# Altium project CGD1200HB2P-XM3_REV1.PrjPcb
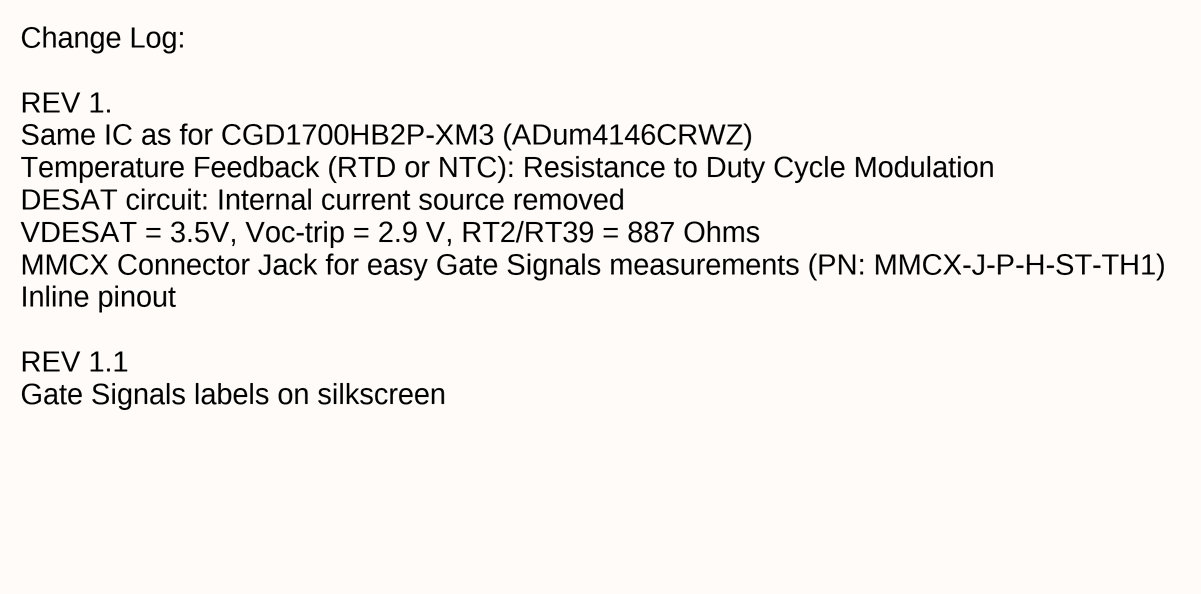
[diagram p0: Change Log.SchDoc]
5 sheets, 178 parts. Net scope: global (net labels, ports and power ports of the same name join across sheets).
Board file: CGD1200HB2P-XM3_REV1.PcbDoc
Sheets:
  Change Log.SchDoc
  Differential Signaling.SchDoc
  Gate Driver.SchDoc
  Power Supplies.SchDoc
  RTD.SchDoc

## Sheet Change Log.SchDoc
size 431 x 279 mm; Organization: ORGANIZATION; Address1: ADDRESS 1; Address2: ADDRESS 2; Address3: ADDRESS 3; Address4: ADDRESS 4; Revision: -; ENG_APP_DATE: --/--/--; DSN_APP_DATE: --/--/--; CHK_APP_DATE: --/--/--

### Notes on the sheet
- Change Log:
  REV 1.
  Same IC as for CGD1700HB2P-XM3 (ADum4146CRWZ)                                                                                                                                                                                                                  Temperature Feedback (RTD or NTC): Resistance to Duty Cycle Modulation                                                                                                                                                                                                     DESAT circuit: Internal current source removed                                                                                      VDESAT = 3.5V, Voc-trip = 2.9 V, RT2/RT39 = 887 Ohms	                                                                            MMCX Connector Jack for easy Gate Signals measurements (PN: MMCX-J-P-H-ST-TH1)
  Inline pinout
  REV 1.1
  Gate Signals labels on silkscreen

## Sheet Differential Signaling.SchDoc
size 431 x 279 mm; Organization: ORGANIZATION; Address1: ADDRESS 1; Address2: ADDRESS 2; Address3: ADDRESS 3; Address4: ADDRESS 4; Revision: -; ENG_APP_DATE: --/--/--; DSN_APP_DATE: --/--/--; CHK_APP_DATE: --/--/--
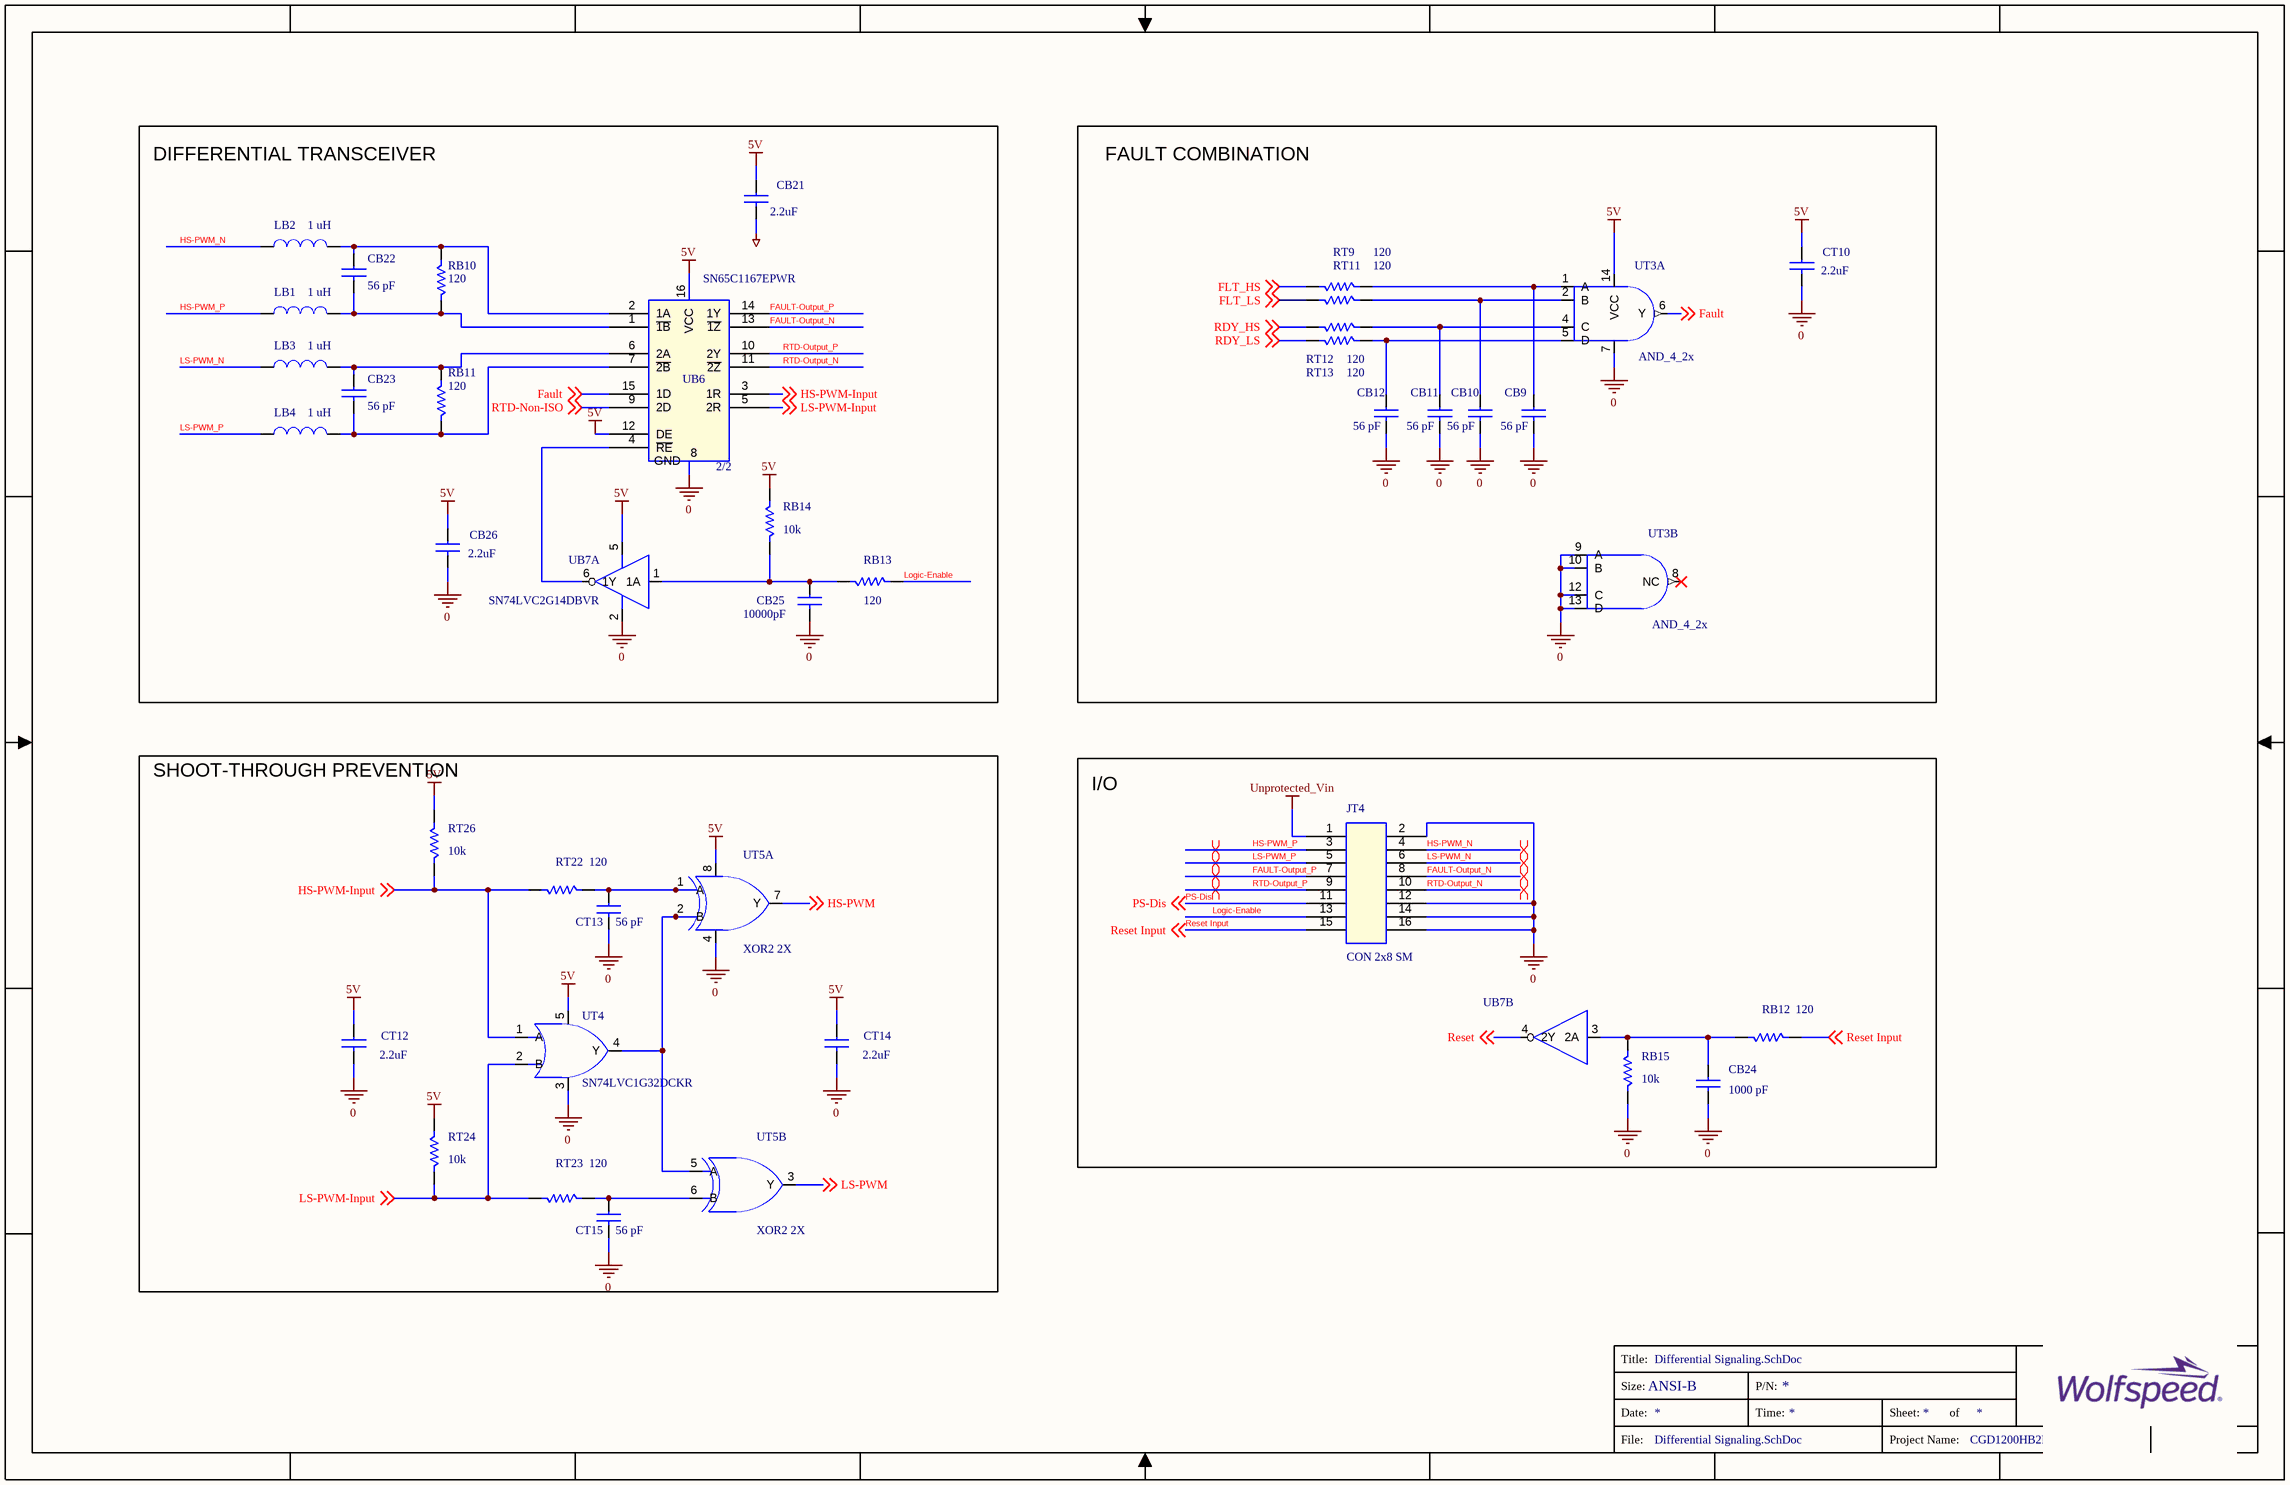
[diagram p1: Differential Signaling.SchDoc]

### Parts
CB9  56 pF  [CAPC1608X90N]
CB10  56 pF  [CAPC1608X90N]
CB11  56 pF  [CAPC1608X90N]
CB12  56 pF  [CAPC1608X90N]
CB21  2.2uF  [CAPC1608X90N]
CB22  56 pF  [CAPC1608X90N]
CB23  56 pF  [CAPC1608X90N]
CB24  1000 pF  [CAPC1608X90N]
CB25  10000pF  [CAPC1608X90N]
CB26  2.2uF  [CAPC1608X90N]
CT10  2.2uF  [CAPC1608X90N]
CT12  2.2uF  [CAPC1608X90N]
CT13  56 pF  [CAPC1608X90N]
CT14  2.2uF  [CAPC1608X90N]
CT15  56 pF  [CAPC1608X90N]
JT4  CON 2x8 SM  [CONN16_3020-16-0300-00_CNC]
LB1  1 uH  [INDC1608X95N]
LB2  1 uH  [INDC1608X95N]
LB3  1 uH  [INDC1608X95N]
LB4  1 uH  [INDC1608X95N]
RB10  120  [RESC1608X55N]
RB11  120  [RESC1608X55N]
RB12  120  [RESC1608X55N]
RB13  120  [RESC1608X55N]
RB14  10k  [RESC1608X55N]
RB15  10k  [RESC1608X55N]
RT9  120  [RESC1608X55N]
RT11  120  [RESC1608X55N]
RT12  120  [RESC1608X55N]
RT13  120  [RESC1608X55N]
RT22  120  [RESC1608X55N]
RT23  120  [RESC1608X55N]
RT24  10k  [RESC1608X55N]
RT26  10k  [RESC1608X55N]
UB6  2/2  Manufacturer PN: SN65C1167EPWR  [tssop_16]
UB7  SN74LVC2G14DBVR  [SOT95P280X145-6N_1]  (parts A,B of 2)
UT3  AND_4_2x  [D14]  (parts A,B of 2)
UT4  SN74LVC1G32DCKR  [SOT65P210X110-5N]
UT5  XOR2 2X  [US8_2P40X2P10_ONS]  (parts A,B of 2)

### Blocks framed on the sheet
DIFFERENTIAL TRANSCEIVER: CB21-CB23 CB25 CB26 LB1-LB4 RB10 RB11 RB13 RB14 UB6 UB7
FAULT COMBINATION: CB9-CB12 CT10 RT9 RT11-RT13 UT3
SHOOT-THROUGH PREVENTION: CT12-CT15 RT22-RT24 RT26 UT4 UT5
I/O: CB24 JT4 RB12 RB15 UB7

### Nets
0: CB9.2 CB10.2 CB11.2 CB12.2 CB21.2 CB24.2 CB25.2 CB26.2 CT10.2 CT12.2 CT13.2 CT14.2 CT15.2 JT4.2 JT4.12 JT4.14 JT4.16 RB15.1 UB6.8(GND) UB7.2(GND) UT3.7(GND) UT3.9(A) UT3.10(B) UT3.12(C) UT3.13(D) UT4.3(GND) UT5.4(GND)  [also labelled GND]
5V: CB21.1 CB26.1 CT10.1 CT12.1 CT14.1 RB14.2 RT24.2 RT26.2 UB6.12(DE) UB6.16(VCC) UB7.5(Vcc) UT3.14(VCC) UT4.5(Vcc) UT5.8(VCC)  [also labelled VCC]
Unprotected_Vin: JT4.1
Fault: UB6.15(1D) UT3.6(Y) ; off-sheet Fault
FAULT-Output_N: JT4.8 UB6.13(~{1Z})
FAULT-Output_P: JT4.7 UB6.14(1Y)
FLT_HS: RT9.1 ; off-sheet FLT_HS
FLT_LS: RT11.1 ; off-sheet FLT_LS
HS-PWM: UT5.7(Y) ; off-sheet HS-PWM
HS-PWM-Input: RT22.1 RT26.1 UB6.3(1R) UT4.1(A) ; off-sheet HS-PWM-Input
HS-PWM_N: JT4.4 LB2.1
HS-PWM_P: JT4.3 LB1.1
Logic-Enable: JT4.13 RB13.2
LS-PWM: UT5.3(Y) ; off-sheet LS-PWM
LS-PWM-Input: RT23.1 RT24.1 UB6.5(2R) UT4.2(B) ; off-sheet LS-PWM-Input
LS-PWM_N: JT4.6 LB3.1
LS-PWM_P: JT4.5 LB4.1
PS-Dis: JT4.11 ; off-sheet PS-Dis
RDY_HS: RT12.1 ; off-sheet RDY_HS
RDY_LS: RT13.1 ; off-sheet RDY_LS
Reset: UB7.4(2Y) ; off-sheet Reset
Reset Input: JT4.15 RB12.2 ; off-sheet Reset Input
RTD-Non-ISO: UB6.9(2D) ; off-sheet RTD-Non-ISO
RTD-Output_N: JT4.10 UB6.11(~{2Z})
RTD-Output_P: JT4.9 UB6.10(2Y)
NetCB9_1: CB9.1 RT9.2 UT3.1(A)
NetCB10_1: CB10.1 RT11.2 UT3.2(B)
NetCB11_1: CB11.1 RT12.2 UT3.4(C)
NetCB12_1: CB12.1 RT13.2 UT3.5(D)
NetCB22_1: CB22.1 LB2.2 RB10.2 UB6.2(1A)
NetCB22_2: CB22.2 LB1.2 RB10.1 UB6.1(~{1B})
NetCB23_1: CB23.1 LB3.2 RB11.2 UB6.6(2A)
NetCB23_2: CB23.2 LB4.2 RB11.1 UB6.7(~{2B})
NetCB24_1: CB24.1 RB12.1 RB15.2 UB7.3(2A)
NetCB25_1: CB25.1 RB13.1 RB14.1 UB7.1(1A)
NetCT13_1: CT13.1 RT22.2 UT5.1(A)
NetCT15_1: CT15.1 RT23.2 UT5.6(B)
NetUB6_4: UB6.4(~{RE}) UB7.6(1Y)
NetUT4_4: UT4.4(Y) UT5.2(B) UT5.5(A)

Not connected (* = marked no-connect by the designer): UT3 3(NC2) 8(NC)* 11(NC)

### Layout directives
differential pair: FAULT-Output_N, FAULT-Output_P, HS-PWM_N, HS-PWM_P, LS-PWM_N, LS-PWM_P, RTD-Output_N, RTD-Output_P

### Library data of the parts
CB9 CB10 = CAP_Dup1: CAP CER 56PF 50V C0G/NP0 0603; Manufacturer: Samsung Electro-Mechanics; Manufacturer PN: CL10C560JB8NNNC; Dielectric Type: Capacitors; Temperature Coefficient: C0G, NP0; Tolerance: 5%; CLASS: DISCRETE
CB11 CB12 CB22 CB23 CT13 CT15 = CAP_Dup1: CAP CER 56PF 50V C0G/NP0 0603; Manufacturer PN: CL10C560JB8NNNC; Manufacturer: Samsung Electro-Mechanics; CLASS: DISCRETE; Tolerance: 5%; Temperature Coefficient: C0G, NP0; Dielectric Type: Capacitors
CB21 CT10 CT12 CT14 = CAP_2.2uF: CAP CER 2.2UF 50V X5R 0603; Company Part Status: Obsolete; Manufacturer: Murata Electronics North America; Manufacturer PN: GRT188R61H225ME13D; Tolerance: 20%; CLASS: DISCRETE
CB24 = CAP_Dup1: CAP CER 1000PF 50V C0G/NP0 0603; Manufacturer PN: CL10C102JB8NNNC; Manufacturer: Samsung Electro-Mechanics; CLASS: DISCRETE; Tolerance: 5%; Temperature Coefficient: C0G, NP0; Dielectric Type: Capacitors
CB25 = CAP: CAP CER 10000PF 25V 10% X7R 0603; Manufacturer PN: CL10B103KA8NNNC; Manufacturer: Samsung Electro-Mechanics America, Inc.; PART_NUMBER: TMP-566; Company Part Status: New; CLASS: DISCRETE; Dielectric Type: Capacitors
CB26 = CAP_2.2uF: CAP CER 2.2UF 50V X5R 0603; Manufacturer PN: GRT188R61H225ME13D; Manufacturer: Murata Electronics North America; Company Part Status: Obsolete; CLASS: DISCRETE; Tolerance: 20%
JT4 = CON16A_Corrected: CONN HEADER SMD 16POS 2.54MM; Manufacturer: Sullins Connector Solutions; Manufacturer PN: SBH11-NBPC-D08-SM-BK; Company Part Status: Released; CLASS: IO; PCB Footprint: CON_2x8_shrouded_SM
LB1-LB3 = INDUCTOR: FIXED IND 1UH 600MA 150 MOHM SMD; Manufacturer PN: MLZ1608A1R0WT000; Manufacturer: TDK Corporation; CLASS: DISCRETE; Tolerance: 20%
LB4 = INDUCTOR: FIXED IND 1UH 600MA 150 MOHM SMD; Manufacturer: TDK Corporation; Manufacturer PN: MLZ1608A1R0WT000; Tolerance: 20%; CLASS: DISCRETE
RB10-RB12 RT9 RT11-RT13 = RES_1: RES SMD 120 OHM 1% 1/10W 0603; Manufacturer PN: RC0603FR-07120RL; Manufacturer: Yageo; PART_NUMBER: TMP-957; Company Part Status: Released; CLASS: DISCRETE; Rated Power: 0.1W, 1/10W; Temperature Coefficient: 100ppm/C
RB13 RT22 RT23 = RES_1: RES SMD 120 OHM 1% 1/10W 0603; PART_NUMBER: TMP-957; Manufacturer: Yageo; Manufacturer PN: RC0603FR-07120RL; Company Part Status: Released; Temperature Coefficient: 100ppm/C; Rated Power: 0.1W, 1/10W; CLASS: DISCRETE
RB14 RT26 = RES: RES SMD 10K OHM 1% 1/10W 0603; Manufacturer PN: ERJ-3EKF1002V; Manufacturer: Panasonic Electronic Components; Company Part Status: New; PART_NUMBER: TMP-788; CLASS: DISCRETE; Rated Power: 0.1W, 1/10W; Temperature Coefficient: 100ppm/C
RB15 = RES: RES SMD 10K OHM 1% 1/10W 0603; Manufacturer: Panasonic Electronic Components; Company Part Status: New; PART_NUMBER: TMP-788; CLASS: DISCRETE; Rated Power: 0.1W, 1/10W; Temperature Coefficient: 100ppm/C
RT24 = RES: RES SMD 10K OHM 1% 1/10W 0603; PART_NUMBER: TMP-788; Company Part Status: New; Manufacturer: Panasonic Electronic Components; Manufacturer PN: ERJ-3EKF1002V; Temperature Coefficient: 100ppm/C; Rated Power: 0.1W, 1/10W; CLASS: DISCRETE
UB6 = SN65C1167: IC DIFF DVR/RCVR DUAL 16-TSSOP; Manufacturer: Texas Instruments; Company Part Status: Released; Supply Voltage: 4.5V ~ 5.5V
UB7 = SN74LVC2G04: IC INVERTER DUAL SHMT-T SOT-23-6; PART_NUMBER: TMP-658; Manufacturer: Texas Instruments; PCB Footprint: SOT_23_6; Supply Voltage: 1.65 V - 5.5 V
UT3 = AND4_2X: IC GATE AND 2CH 4-INP 14SOIC; Company Part Status: Released; Manufacturer: Texas Instruments; Manufacturer PN: SN74HC21DR; Supply Voltage: 2 V - 6 V
UT4 = SN74LVC1G32: IC GATE OR 1CH 2-INP SC-70-5; Manufacturer: Texas Instruments; PART_NUMBER: TMP-446; PCB Footprint: SC70_5; Supply Voltage: 1.65 V - 5.5 V
UT5 = XOR2_2X: IC GATE XOR 2CH 2-INP US8; Manufacturer PN: NL27WZ86USG; Manufacturer: ON Semiconductor; Company Part Status: Released; PCB Footprint: US8_2P40X2P10; Supply Voltage: 1.65 V ~ 5.5 V

## Sheet Gate Driver.SchDoc
size 431 x 279 mm; Organization: ORGANIZATION; Address1: ADDRESS 1; Address2: ADDRESS 2; Address3: ADDRESS 3; Address4: ADDRESS 4; Revision: -; ENG_APP_DATE: --/--/--; DSN_APP_DATE: --/--/--; CHK_APP_DATE: --/--/--
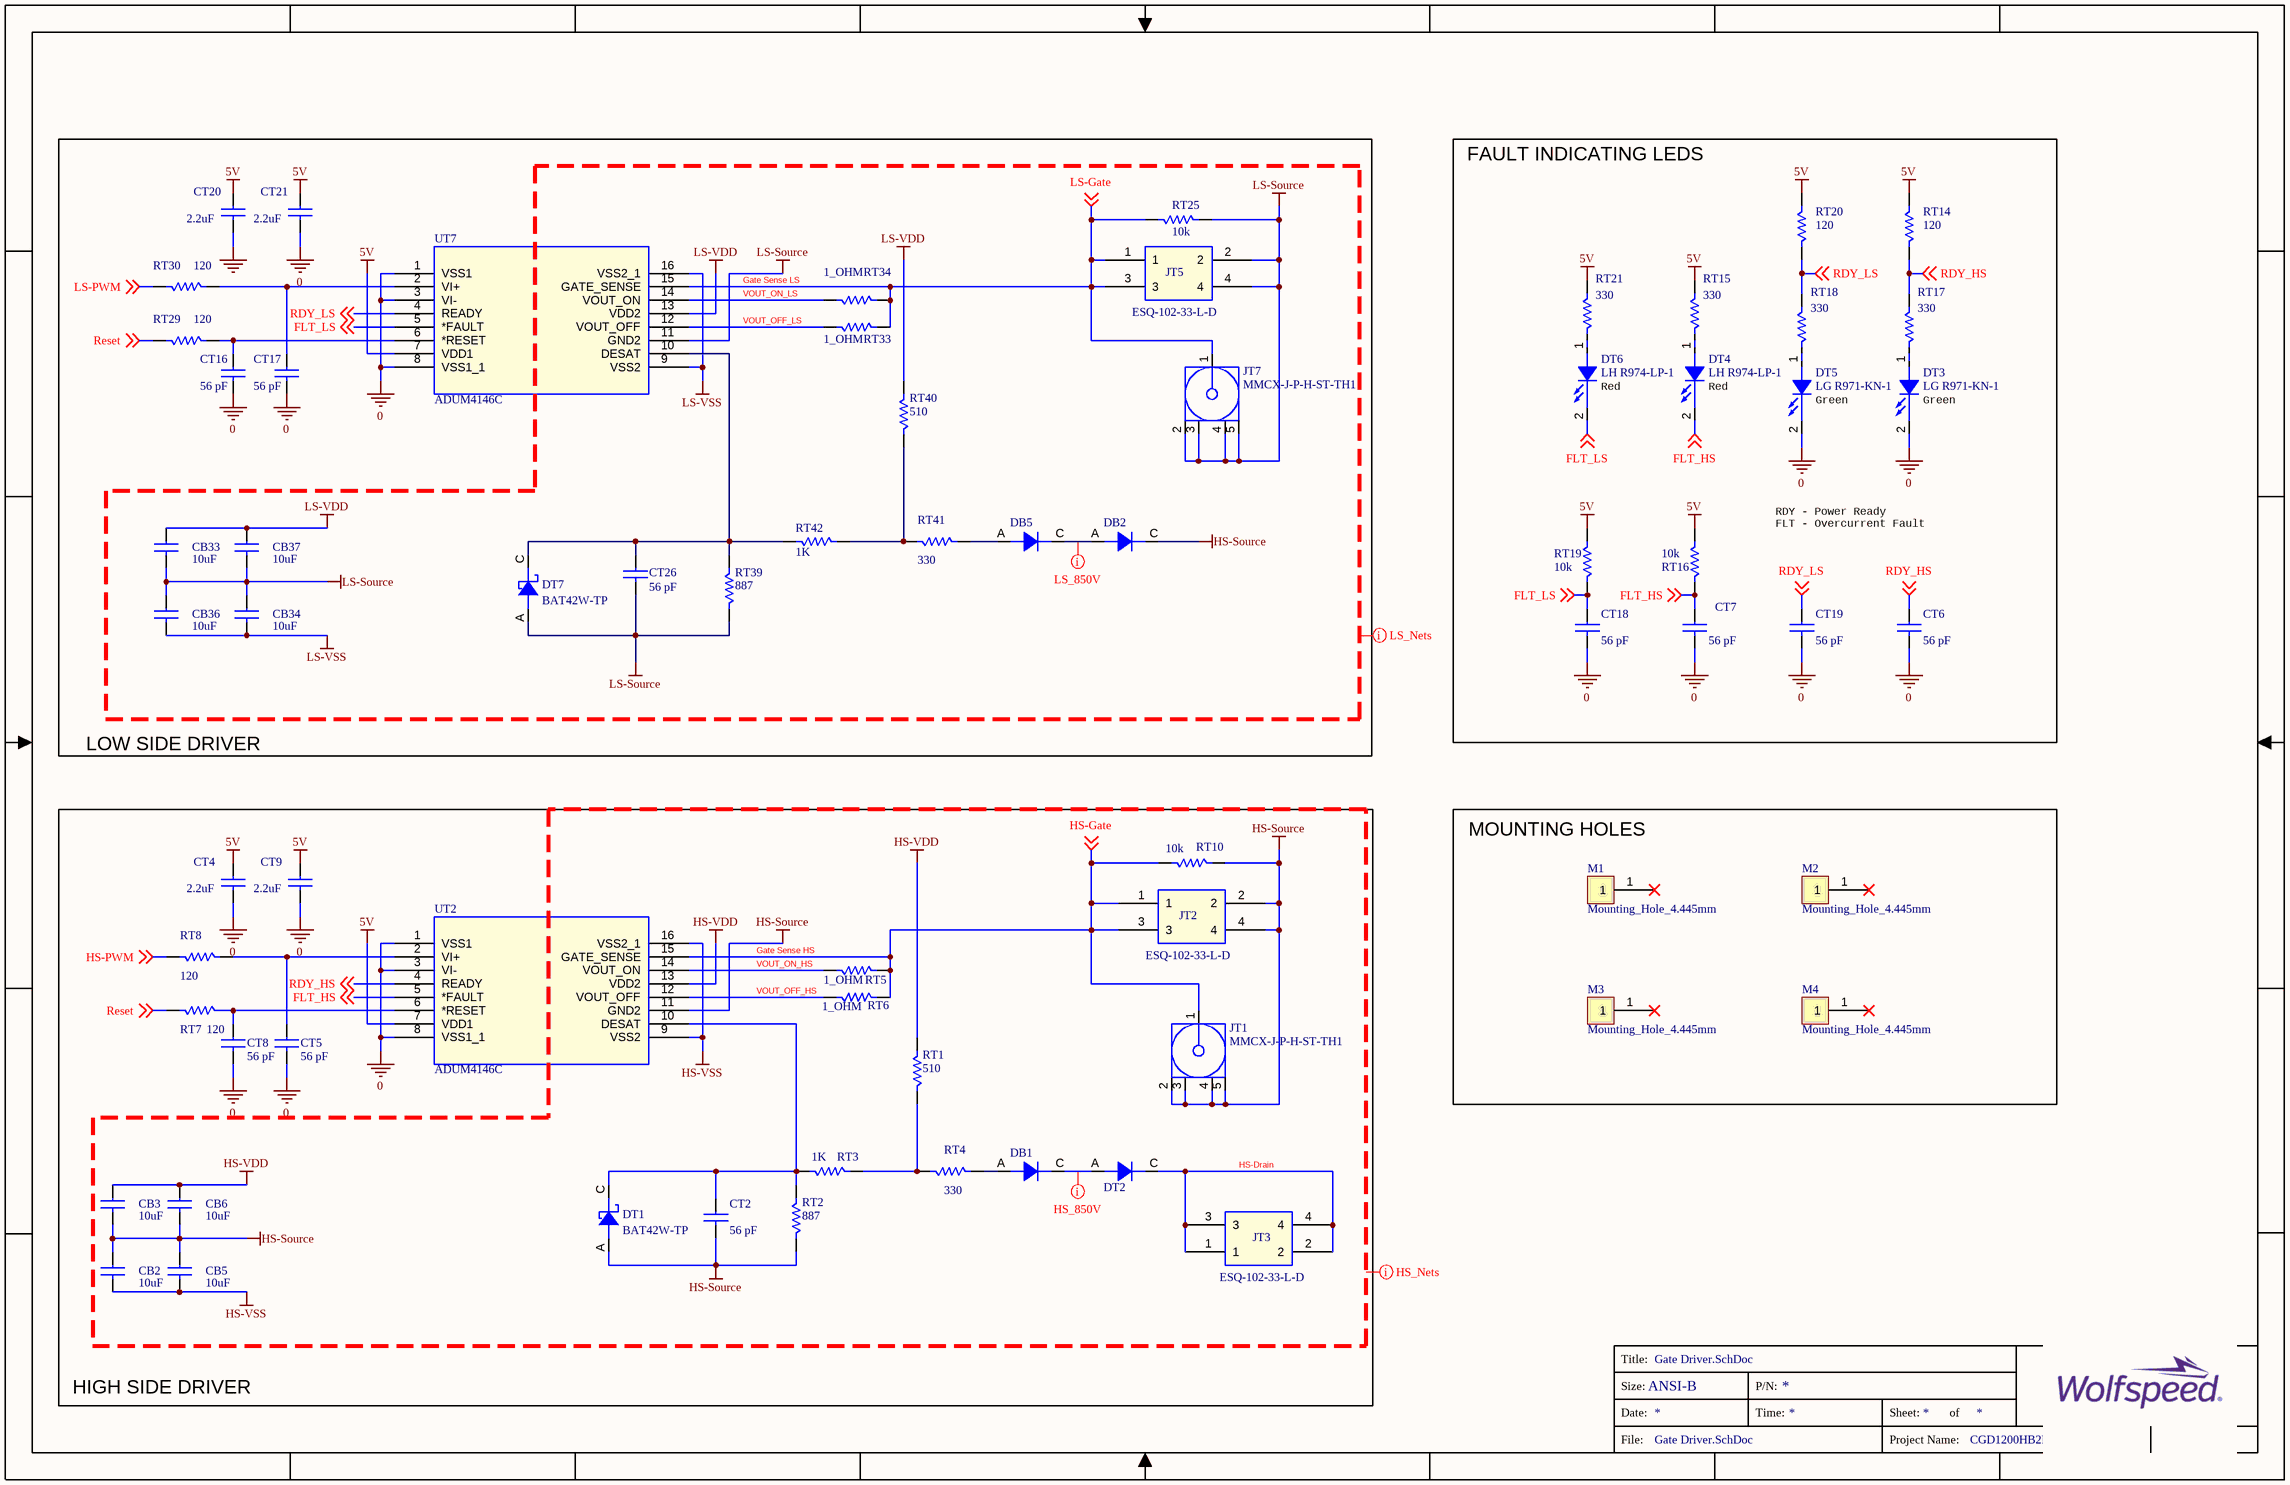
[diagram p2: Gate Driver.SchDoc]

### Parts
CB2  10uF  [C_1206]
CB3  10uF  [C_1206]
CB5  10uF  [C_1206]
CB6  10uF  [C_1206]
CB33  10uF  [C_1206]
CB34  10uF  [C_1206]
CB36  10uF  [C_1206]
CB37  10uF  [C_1206]
CT2  56 pF  [CAPC1608X90N]
CT4  2.2uF  [CAPC1608X90N]
CT5  56 pF  [CAPC1608X90N]
CT6  56 pF  [CAPC1608X90N]
CT7  56 pF  [CAPC1608X90N]
CT8  56 pF  [CAPC1608X90N]
CT9  2.2uF  [CAPC1608X90N]
CT16  56 pF  [CAPC1608X90N]
CT17  56 pF  [CAPC1608X90N]
CT18  56 pF  [CAPC1608X90N]
CT19  56 pF  [CAPC1608X90N]
CT20  2.2uF  [CAPC1608X90N]
CT21  2.2uF  [CAPC1608X90N]
CT26  56 pF  [CAPC1608X90N]
DB1  US3M-13  [DO-214AB-SMC]  (value not drawn)
DB2  US3M-13  [DO-214AB-SMC]  (value not drawn)
DB5  US3M-13  [DO-214AB-SMC]  (value not drawn)
DT1  BAT42W-TP  [sod123]
DT2  US3M-13  [DO-214AB-SMC]  (value not drawn)
DT3  LG R971-KN-1  [D_0805]
DT4  LH R974-LP-1  [D_0805]
DT5  LG R971-KN-1  [D_0805]
DT6  LH R974-LP-1  [D_0805]
DT7  BAT42W-TP  [sod123]
JT1  MMCX-J-P-H-ST-TH1  [MMCX-J-P-H-ST-TH1_PCB]
JT2  ESQ-102-33-L-D  [CON_2x2_100mil_TH]
JT3  ESQ-102-33-L-D  [CON_2x2_100mil_TH - NEW]
JT5  ESQ-102-33-L-D  [CON_2x2_100mil_TH]
JT7  MMCX-J-P-H-ST-TH1  [MMCX-J-P-H-ST-TH1_PCB]
M1  Mounting_Hole_4.445mm  [Mounting_Hole]
M2  Mounting_Hole_4.445mm  [Mounting_Hole]
M3  Mounting_Hole_4.445mm  [Mounting_Hole]
M4  Mounting_Hole_4.445mm  [Mounting_Hole]
RT1  510  [RESC2012X06N_510_698]
RT2  887  [RESC2012X06N_510_698]
RT3  1K  [RESC1608X55N]
RT4  330  [RESC1608X55N]
RT5  1_OHM  [RESC6432X70N]
RT6  1_OHM  [RESC6432X70N]
RT7  120  [RESC1608X55N]
RT8  120  [RESC1608X55N]
RT10  10k  [RESC1608X55N]
RT14  120  [RESC1608X55N]
RT15  330  [RESC1608X55N]
RT16  10k  [RESC1608X55N]
RT17  330  [RESC1608X55N]
RT18  330  [RESC1608X55N]
RT19  10k  [RESC1608X55N]
RT20  120  [RESC1608X55N]
RT21  330  [RESC1608X55N]
RT25  10k  [RESC1608X55N]
RT29  120  [RESC1608X55N]
RT30  120  [RESC1608X55N]
RT33  1_OHM  [RESC6432X70N]
RT34  1_OHM  [RESC6432X70N]
RT39  887  [RESC2012X06N_510_698]
RT40  510  [RESC2012X06N_510_698]
RT41  330  [RESC1608X55N]
RT42  1K  [RESC1608X55N]
UT2  ADUM4146C  [SOIC127P1032X265-16N]
UT7  ADUM4146C  [SOIC127P1032X265-16N]

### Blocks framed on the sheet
LOW SIDE DRIVER: CB33 CB34 CB36 CB37 CT16 CT17 CT20 CT21 CT26 DB2 DB5 DT7 JT5 JT7 RT25 RT29 RT30 RT33 RT34 RT39-RT42 UT7
FAULT INDICATING LEDS: CT6 CT7 CT18 CT19 DT3-DT6 RT14-RT21
HIGH SIDE DRIVER: CB2 CB3 CB5 CB6 CT2 CT4 CT5 CT8 CT9 DB1 DT1 DT2 JT1-JT3 RT1-RT8 RT10 UT2
MOUNTING HOLES: M1-M4

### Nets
0: CT4.2 CT5.2 CT6.2 CT7.2 CT8.2 CT9.2 CT16.2 CT17.2 CT18.2 CT19.2 CT20.2 CT21.2 DT3.2(C) DT5.2(C) UT2.1(VSS1) UT2.3(VI-) UT2.8(VSS1_1) UT7.1(VSS1) UT7.3(VI-) UT7.8(VSS1_1)
5V: CT4.1 CT9.1 CT20.1 CT21.1 RT14.1 RT15.2 RT16.1 RT19.1 RT20.1 RT21.2 UT2.7(VDD1) UT7.7(VDD1)
HS-Source: CB2.1 CB3.2 CB5.1 CB6.2 CT2.2 DB2.C(CATHODE) DT1.A JT1.2(GND) JT1.3(GND) JT1.4(GND) JT1.5(GND) JT2.2 JT2.4 RT2.2 RT10.2 UT2.11(GND2)
HS-VDD: CB3.1 CB6.1 RT1.1 UT2.13(VDD2)
HS-VSS: CB2.2 CB5.2 UT2.9(VSS2) UT2.16(VSS2_1)
LS-Source: CB33.2 CB34.1 CB36.1 CB37.2 CT26.2 DT7.A JT5.2 JT5.4 JT7.2(GND) JT7.3(GND) JT7.4(GND) JT7.5(GND) RT25.2 RT39.2 UT7.11(GND2)
LS-VDD: CB33.1 CB37.1 RT40.1 UT7.13(VDD2)
LS-VSS: CB34.2 CB36.2 UT7.9(VSS2) UT7.16(VSS2_1)
FLT_HS: CT7.1 DT4.2(C) RT16.2 UT2.5(*FAULT) ; off-sheet FLT_HS
FLT_LS: CT18.1 DT6.2(C) RT19.2 UT7.5(*FAULT) ; off-sheet FLT_LS
Gate Sense HS: JT1.1(SIGNAL) JT2.1 JT2.3 RT5.2 RT6.2 RT10.1 UT2.15(GATE_SENSE) ; off-sheet HS-Gate  [also labelled HS-Gate]
Gate Sense LS: JT5.1 JT5.3 JT7.1(SIGNAL) RT25.1 RT33.2 RT34.2 UT7.15(GATE_SENSE) ; off-sheet LS-Gate  [also labelled LS-Gate]
HS-Drain: DT2.C(CATHODE) JT3.1 JT3.2 JT3.3 JT3.4
HS-PWM: RT8.1 ; off-sheet HS-PWM
LS-PWM: RT30.1 ; off-sheet LS-PWM
RDY_HS: CT6.1 RT14.2 RT17.2 UT2.4(READY) ; off-sheet RDY_HS
RDY_LS: CT19.1 RT18.2 RT20.2 UT7.4(READY) ; off-sheet RDY_LS
Reset: RT7.1 RT29.1 ; off-sheet Reset
VOUT_OFF_HS: RT6.1 UT2.12(VOUT_OFF)
VOUT_OFF_LS: RT33.1 UT7.12(VOUT_OFF)
VOUT_ON_HS: RT5.1 UT2.14(VOUT_ON)
VOUT_ON_LS: RT34.1 UT7.14(VOUT_ON)
NetCT2_1: CT2.1 DT1.C RT2.1 RT3.2 UT2.10(DESAT)
NetCT5_1: CT5.1 RT8.2 UT2.2(VI+)
NetCT8_1: CT8.1 RT7.2 UT2.6(*RESET)
NetCT16_1: CT16.1 RT29.2 UT7.6(*RESET)
NetCT17_1: CT17.1 RT30.2 UT7.2(VI+)
NetCT26_1: CT26.1 DT7.C RT39.1 RT42.2 UT7.10(DESAT)
NetDB1_A: DB1.A(ANODE) RT4.1
NetDB1_C: DB1.C(CATHODE) DT2.A(ANODE)
NetDB2_A: DB2.A(ANODE) DB5.C(CATHODE)
NetDB5_A: DB5.A(ANODE) RT41.1
NetDT3_1: DT3.1(A) RT17.1
NetDT4_1: DT4.1(A) RT15.1
NetDT5_1: DT5.1(A) RT18.1
NetDT6_1: DT6.1(A) RT21.1
NetRT1_2: RT1.2 RT3.1 RT4.2
NetRT40_2: RT40.2 RT41.2 RT42.1

Not connected (* = marked no-connect by the designer): M1 1*; M2 1*; M3 1*; M4 1*

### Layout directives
net class LS_Nets: 0, 5V, FLT_LS, Gate Sense LS, HS-Source, LS-Gate, LS-PWM, LS-Source, LS-VDD, LS-VSS, RDY_LS, Reset, VOUT_OFF_LS, VOUT_ON_LS
net class HS_Nets: 0, 5V, FLT_HS, Gate Sense HS, HS-Drain, HS-Gate, HS-PWM, HS-Source, HS-VDD, HS-VSS, RDY_HS, Reset, VOUT_OFF_HS, VOUT_ON_HS
net class LS_850V: NetDB2_A
net class HS_850V: NetDB1_C

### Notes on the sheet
- (near DT6) Red
- (near DT4) Red
- (near DT5) Green
- (near DT3) Green
- RDY - Power Ready
  FLT - Overcurrent Fault

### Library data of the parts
CB2 CB3 CB33 CB36 = CAP_10uF: CAP CER 10UF 16V X7R 1206; Company Part Status: New; PART_NUMBER: TMP-885; Manufacturer: Murata Electronics North America; Manufacturer PN: GCM31CR71C106KA64L; Dielectric Type: Capacitors; Tolerance: 10%; CLASS: DISCRETE
CB5 CB6 CB34 CB37 = CAP_10uF: CAP CER 10UF 16V X7R 1206; Company Part Status: New; Manufacturer PN: GCM31CR71C106KA64L; Manufacturer: Murata Electronics North America; PART_NUMBER: TMP-885; CLASS: DISCRETE; Tolerance: 10%; Dielectric Type: Capacitors
CT2 CT5 CT6 CT8 CT17 CT19 CT26 = CAP_Dup1: as CB11 on sheet Differential Signaling
CT4 CT9 CT20 CT21 = CAP_2.2uF: as CB21 on sheet Differential Signaling
CT7 CT16 CT18 = CAP_Dup1: as CB9 on sheet Differential Signaling
DB1 DB2 DB5 = US3M-13: DIODE GEN PURP 1KV 3A SMC; Manufacturer: Diodes; Average Rectified Current: 1A; Reverse Recovery Time: 75ns; Element Configuration: Single; Max Forward Surge Current (Ifsm): 30A
DT1 DT7 = DIODE_SCHOTTKY_11: DIODE SCHOTTKY 30V 200MA SOD123; Company Part Status: Released; Manufacturer: Micro Commercial Co; CLASS: DISCRETE
DT2 = US3M-13_TOP: DIODE GEN PURP 1KV 3A SMC; Average Rectified Current: 1A; Reverse Recovery Time: 75ns; Element Configuration: Single; Max Forward Surge Current (Ifsm): 30A
DT3 = LED: LED GREEN DIFFUSED 0805 SMD; PART_NUMBER: TMP-915; Manufacturer: OSRAM Opto Semiconductors Inc.; Rated Voltage: 2.2V; CLASS: DISCRETE
DT4 DT6 = LED_1: LED RED DIFFUSED 0805 SMD; Manufacturer: OSRAM Opto Semiconductors Inc.; PART_NUMBER: TMP-917; CLASS: DISCRETE; Rated Voltage: 1.8V @ 20mA
DT5 = LED: LED GREEN DIFFUSED 0805 SMD; Manufacturer: OSRAM Opto Semiconductors Inc.; PART_NUMBER: TMP-915; CLASS: DISCRETE; Rated Voltage: 2.2V
JT1 JT7 = MMCX-J-P-H-ST-TH1: CONN MMCX JACK STR 50 OHM PCB; Manufacturer: Samtec; Body Plating: Gold; Body Material: Brass; Frequency: 6Hz; Impedance: 50R; Operating Frequency: 0 to 6Hz
JT2 JT5 = CON_2x2_100mil: Conn Elevated Socket SKT 4 POS 2.54mm Solder ST Thru-Hole; Manufacturer: Samtec; CLASS: IO; Number of Contacts: 4; Gender: Receptacle
JT3 = CON_2x2_100mil_NEW: Conn Elevated Socket SKT 4 POS 2.54mm Solder ST Thru-Hole; Manufacturer: Samtec; CLASS: IO; PCB Footprint: CON_2x2_100mil_TH; Number of Contacts: 4; Gender: Receptacle
RT1 RT40 = RES_7: RES SMD 510 OHM 1% 0.4W 0805; Manufacturer: Vishay Dale; Manufacturer Part Number: RCS0805510RFKEA; Resistance: 510R; Max Power Dissipation: 400mW; Temperature Coefficient: 100ppm/°C
RT2 = RES_8_887: RES 887 OHM 1% 1/8W 0805; Manufacturer: Stackpole Electronics; Manufacturer Part Number: RMCF0805FT887R; Resistance: 887R; Max Power Dissipation: 125mW; Temperature Coefficient: 100ppm/°C
RT3 RT42 = RES_6: RES 1K OHM 1% 1/8W 0603; Manufacturer: Stackpole Electronics; Manufacturer Part Number: RNCP0603FTD1K00; Resistance: 1kR; Max Power Dissipation: 125mW; Temperature Coefficient: 100ppm/°C
RT4 RT17 RT21 RT41 = RES_3: RES SMD 330 OHM 5% 1/10W 0603; Manufacturer PN: RC0603JR-07330RL; Manufacturer: Yageo; Company Part Status: Released; CLASS: DISCRETE; Rated Power: 0.1W, 1/10W; Temperature Coefficient: 100ppm/C
RT5 RT6 = RES_4: RES SMD 1 OHM 1% 1.5W 2512; Company Part Status: Released; Manufacturer: Vishay Dale; Manufacturer PN: CRCW25121R00FKEGHP; Temperature Coefficient: 100ppm/C; CLASS: DISCRETE
RT7 RT8 RT14 RT20 RT29 RT30 = RES_1: RES SMD 120 OHM 1% 1/10W 0603; PART_NUMBER: TMP-957; Company Part Status: Released; Manufacturer: Yageo; Manufacturer PN: RC0603FR-07120RL; Temperature Coefficient: 100ppm/C; Rated Power: 0.1W, 1/10W; CLASS: DISCRETE
RT10 RT16 RT19 RT25 = RES: as RB14 on sheet Differential Signaling
RT15 RT18 = RES_3: RES SMD 330 OHM 5% 1/10W 0603; Company Part Status: Released; Manufacturer: Yageo; Manufacturer PN: RC0603JR-07330RL; Temperature Coefficient: 100ppm/C; Rated Power: 0.1W, 1/10W; CLASS: DISCRETE
RT33 RT34 = RES_4: RES SMD 1 OHM 1% 1.5W 2512; Manufacturer PN: CRCW25121R00FKEGHP; Manufacturer: Vishay Dale; Company Part Status: Released; CLASS: DISCRETE; Temperature Coefficient: 100ppm/C
RT39 = RES_8_887: RES 887 OHM 1% 1/8W 0805; Manufacturer: Stackpole Electronics; Manufacturer Part Number: RMCF0805FT887R; Max Power Dissipation: 125mW; Temperature Coefficient: 100ppm/°C; Resistance: 887R
UT2 UT7 = ADUM4146C: 1500V ISOLATED HI UVLO 14.5V GAT; Manufacturer: Analog Devices; Manufacturer Part Number: ADUM4146CRWZ

## Sheet Power Supplies.SchDoc
size 431 x 279 mm; Organization: ORGANIZATION; Address1: ADDRESS 1; Address2: ADDRESS 2; Address3: ADDRESS 3; Address4: ADDRESS 4; Revision: -; ENG_APP_DATE: --/--/--; DSN_APP_DATE: --/--/--; CHK_APP_DATE: --/--/--
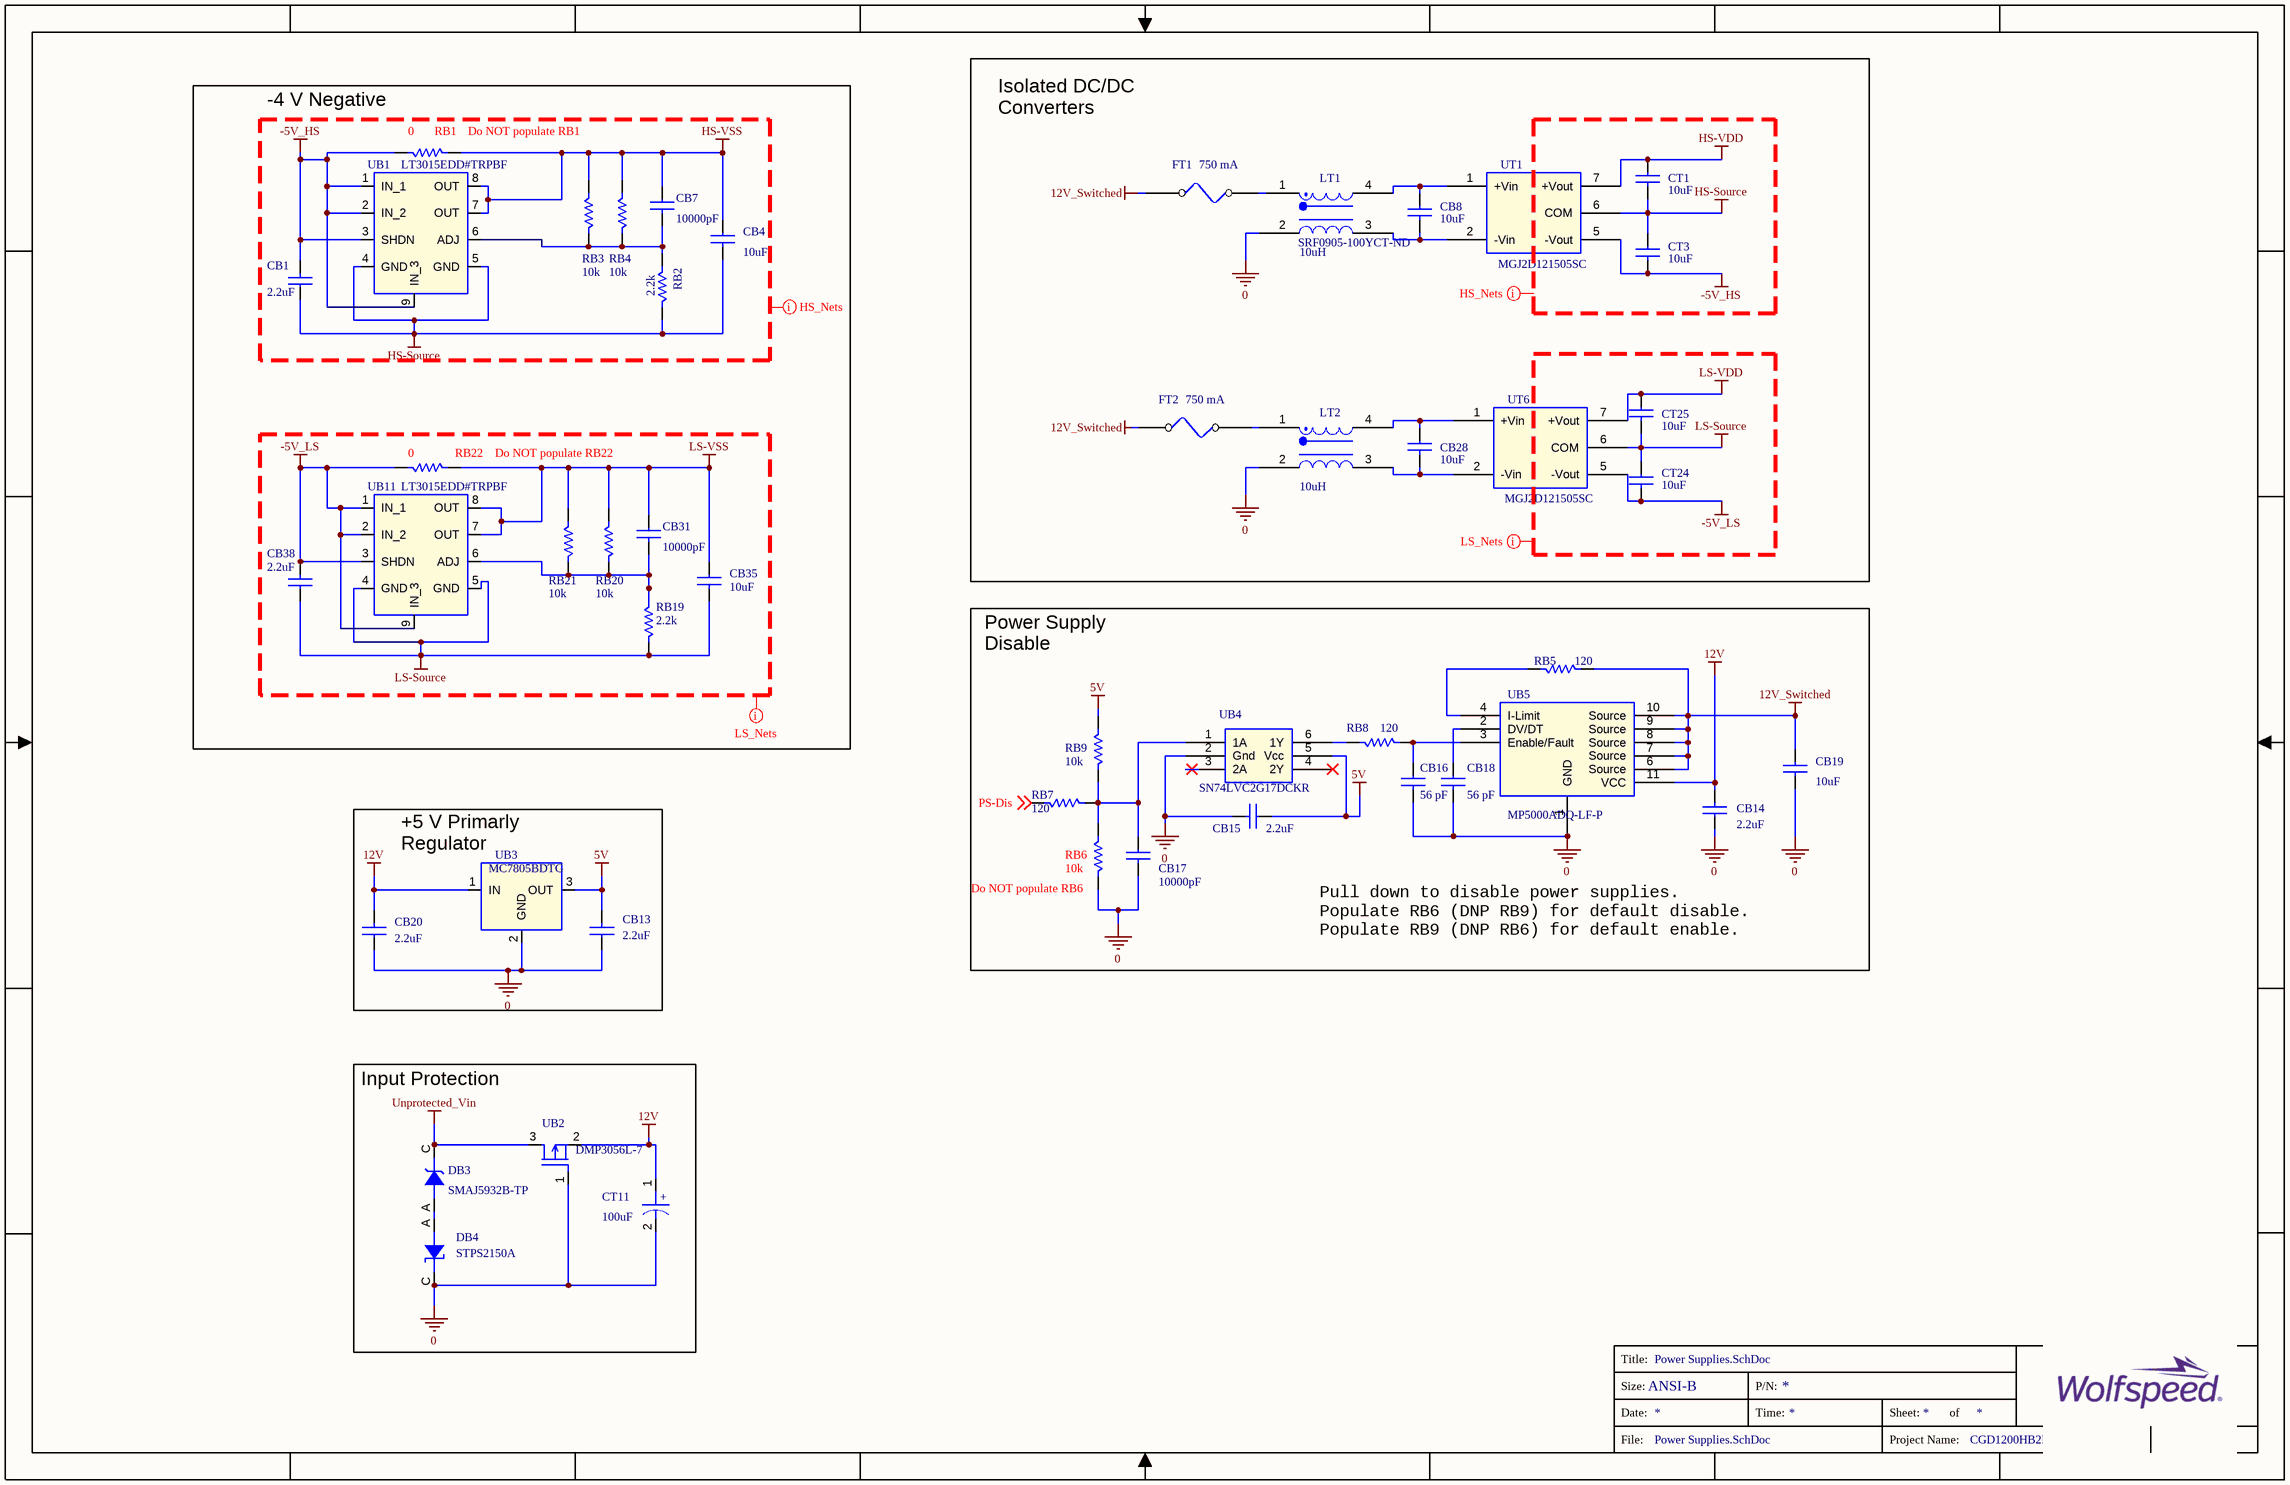
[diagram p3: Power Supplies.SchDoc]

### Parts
CB1  2.2uF  [CAPC1608X90N]
CB4  10uF  [C_1206]
CB7  10000pF  [CAPC1608X90N]
CB8  10uF  [C_1206]
CB13  2.2uF  [CAPC1608X90N]
CB14  2.2uF  [CAPC1608X90N]
CB15  2.2uF  [CAPC1608X90N]
CB16  56 pF  [CAPC1608X90N]
CB17  10000pF  [CAPC1608X90N]
CB18  56 pF  [CAPC1608X90N]
CB19  10uF  [C_1206]
CB20  2.2uF  [CAPC1608X90N]
CB28  10uF  [C_1206]
CB31  10000pF  [CAPC1608X90N]
CB35  10uF  [C_1206]
CB38  2.2uF  [CAPC1608X90N]
CT1  10uF  [C_1206]
CT3  10uF  [C_1206]
CT11  100uF  [CAP_EEE1HA101UP]
CT24  10uF  [C_1206]
CT25  10uF  [C_1206]
DB3  SMAJ5932B-TP  [DIOM4426X24N_DB3]
DB4  STPS2150A  [DIOM4326X26N_DB4]
FT1  750 mA  [FUSE_SMD_SSQ2410]
FT2  750 mA  [FUSE_SMD_SSQ2410]
LT1  10uH  Supplier Part Number 1: SRF0905-100YCT-ND  [SRF0905]
LT2  10uH  [SRF0905]
RB1  0  [RES_2012_SAM]
RB2  2.2k  [RESC1608X55N]
RB3  10k  [RESC1608X55N]
RB4  10k  [RESC1608X55N]
RB5  120  [RESC1608X55N]
RB6  10k  [RESC1608X55N]
RB7  120  [RESC1608X55N]
RB8  120  [RESC1608X55N]
RB9  10k  [RESC1608X55N]
RB19  2.2k  [RESC1608X55N]
RB20  10k  [RESC1608X55N]
RB21  10k  [RESC1608X55N]
RB22  0  [RES_2012_SAM]
UB1  LT3015EDD#TRPBF  [8-WDFN_Exposed_Pad]
UB2  DMP3056L-7  [SOT_23_3]
UB3  MC7805BDTG  [DPAK-3]
UB4  SN74LVC2G17DCKR  [SOT65P210X110-6N_UB4]
UB5  MP5000ADQ-LF-P  [SON50P300X300X100-11N]
UB11  LT3015EDD#TRPBF  [8-WDFN_Exposed_Pad]
UT1  MGJ2D121505SC  [MGJ2D121505SC]
UT6  MGJ2D121505SC  [MGJ2D121505SC]

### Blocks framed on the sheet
Do NOT populate RB6: CB14-CB19 RB5-RB9 UB4 UB5
Input Protection: CT11 DB3 DB4 UB2

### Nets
0: CB13.1 CB14.1 CB15.2 CB16.2 CB17.2 CB18.2 CB19.2 CB20.1 CT11.2 DB4.C LT1.2 LT2.2 RB6.2 UB2.1(G) UB3.2(GND) UB4.2(Gnd) UB5.1(GND)
5V: CB13.2 CB15.1 RB9.1 UB3.3(OUT) UB4.5(Vcc)
12V: CB14.2 CB20.2 CT11.1 UB2.2(S) UB3.1(IN) UB5.11(VCC)
12V_Switched: CB19.1 FT1.1 FT2.1 RB5.1 UB5.6(Source) UB5.7(Source) UB5.8(Source) UB5.9(Source) UB5.10(Source)
-5V_HS: CB1.2 CT3.2 RB1.1 UB1.1(IN_1) UB1.2(IN_2) UB1.3(SHDN) UB1.9(IN_3) UT1.5(-Vout)
-5V_LS: CB38.2 CT24.2 RB22.1 UB11.1(IN_1) UB11.2(IN_2) UB11.3(SHDN) UB11.9(IN_3) UT6.5(-Vout)
HS-Source: CB1.1 CB4.2 CT1.2 CT3.1 RB2.2 UB1.4(GND) UB1.5(GND) UT1.6(COM)
HS-VDD: CT1.1 UT1.7(+Vout)
HS-VSS: CB4.1 CB7.1 RB1.2 RB3.1 RB4.1 UB1.7(OUT) UB1.8(OUT)
LS-Source: CB35.2 CB38.1 CT24.1 CT25.2 RB19.2 UB11.4(GND) UB11.5(GND) UT6.6(COM)
LS-VDD: CT25.1 UT6.7(+Vout)
LS-VSS: CB31.1 CB35.1 RB20.1 RB21.1 RB22.2 UB11.7(OUT) UB11.8(OUT)
Unprotected_Vin: DB3.C UB2.3(D)
PS-Dis: RB7.2 ; off-sheet PS-Dis
NetCB7_2: CB7.2 RB2.1 RB3.2 RB4.2 UB1.6(ADJ)
NetCB8_1: CB8.1 LT1.4 UT1.1(+Vin)
NetCB8_2: CB8.2 LT1.3 UT1.2(-Vin)
NetCB16_1: CB16.1 RB8.1 UB5.3(Enable/Fault)
NetCB17_1: CB17.1 RB6.1 RB7.1 RB9.2 UB4.1(1A)
NetCB18_1: CB18.1 UB5.2(DV/DT)
NetCB28_1: CB28.1 LT2.4 UT6.1(+Vin)
NetCB28_2: CB28.2 LT2.3 UT6.2(-Vin)
NetCB31_2: CB31.2 RB19.1 RB20.2 RB21.2 UB11.6(ADJ)
NetDB3_A: DB3.A DB4.A
NetFT1_2: FT1.2 LT1.1
NetFT2_2: FT2.2 LT2.1
NetRB5_2: RB5.2 UB5.4(I-Limit)
NetRB8_2: RB8.2 UB4.6(1Y)

Not connected (* = marked no-connect by the designer): UB4 3(2A)* 4(2Y)*; UB5 5(NC)

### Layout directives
net class LS_Nets: -5V_LS, LS-Source, LS-VDD, LS-VSS
net class HS_Nets: -5V_HS, HS-Source, HS-VDD, HS-VSS

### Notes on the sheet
- (near RB1) -4 V Negative Regulators
- (near RB1) Do NOT populate RB1
- Isolated DC/DC
  Converters
- Do NOT populate RB22
- Power Supply
  Disable
- (near UB3) +5 V Primarly
  Regulator
- Pull down to disable power supplies.
  Populate RB6 (DNP RB9) for default disable.
  Populate RB9 (DNP RB6) for default enable.

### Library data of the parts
CB1 CB14 CB15 CB20 CB38 = CAP_2.2uF: CAP CER 2.2UF 50V X5R 0603; Company Part Status: Obsolete; Manufacturer PN: GRT188R61H225ME13D; Manufacturer: Murata Electronics North America; CLASS: DISCRETE; Tolerance: 20%
CB4 CB8 CB28 CB35 CT1 CT3 = CAP_10uF: as CB2 on sheet Gate Driver
CB7 CB17 CB31 = CAP: CAP CER 10000PF 25V 10% X7R 0603; Company Part Status: New; PART_NUMBER: TMP-566; Manufacturer: Samsung Electro-Mechanics America, Inc.; Manufacturer PN: CL10B103KA8NNNC; Dielectric Type: Capacitors; CLASS: DISCRETE
CB13 = CAP_2.2uF: as CB26 on sheet Differential Signaling
CB16 CB18 = CAP_Dup1: as CB11 on sheet Differential Signaling
CB19 CT24 CT25 = CAP_10uF: CAP CER 10UF 16V X7R 1206; Manufacturer PN: GCM31CR71C106KA64L; Manufacturer: Murata Electronics North America; PART_NUMBER: TMP-885; Company Part Status: New; CLASS: DISCRETE; Tolerance: 10%; Dielectric Type: Capacitors
CT11 = CAP_100uF: CAP ALUM 100UF 20% 50V SMD; Manufacturer PN: EEE-1HA101UP; Manufacturer: Panasonic Electronic Components; PART_NUMBER: TMP-537; CLASS: DISCRETE; Dielectric Type: Aluminum Electrolitic; PCB Footprint: AlumElec_8mmx10_5mm
DB3 = DIODE_ZENER_3: DIODE ZENER 20V 1.5W DO214AC; Manufacturer: Micro Commercial Co; CLASS: DISCRETE; Tolerance: 5%; Max Reverse Leakage Current: 500nA; Impedance: 14R; Element Configuration: Single; Test Current: 18.7mA; PCB Footprint: SOD123
DB4 = DIODE_SCHOTTKY_13: DIODE SCHOTTKY 150V 2A SMA; PART_NUMBER: TMP-523; Manufacturer: STMicroelectronics; Rated Voltage: 820mV @ 2A; CLASS: DISCRETE; Max Reverse Current: 1.5uA; Peak Non-Repetitive Surge Current: 75A; Element Configuration: Single; Forward Voltage: 890mV; Polarity: Standard
FT1 = FUSE: FUSE BOARD MNT 750MA 125VAC/VDC; Manufacturer PN: SSQ 750; Manufacturer: Bel Fuse Inc.; CLASS: DISCRETE
FT2 = FUSE: FUSE BOARD MNT 750MA 125VAC/VDC; Manufacturer: Bel Fuse Inc.; Manufacturer PN: SSQ 750; CLASS: DISCRETE
LT1 LT2 = CM choke - LPD3015_2: INDUCTOR COMMON MODE 10UH 1.6A; Manufacturer: Bourns Inc.; PART_NUMBER: TMP-846; Manufacturer PN: SRF0905-100Y; CLASS: DISCRETE
RB1 = RES_5: RES SMD 0 OHM JUMPER 1/8W 0805; Manufacturer: Samsung Electro-Mechanics; Manufacturer PN: RC2012J000CS; Rated Power: 0.125W, 1/8W; CLASS: DISCRETE; PCB Footprint: RESC2012X70N
RB2 RB19 = RES_2_BOT: RES SMD 2.2K OHM 1% 1/10W 0603; Company Part Status: New; Manufacturer: Yageo; Manufacturer PN: RC0603FR-072K2L; Temperature Coefficient: 100ppm/C; Rated Power: 0.1W, 1/10W; CLASS: DISCRETE
RB3 RB4 RB9 RB20 RB21 = RES: as RB14 on sheet Differential Signaling
RB5 RB7 = RES_1: as RB10 on sheet Differential Signaling
RB6 = RES: as RT24 on sheet Differential Signaling
RB8 = RES_1: as RB13 on sheet Differential Signaling
RB22 = RES_5: RES SMD 0 OHM JUMPER 1/8W 0805; Manufacturer PN: RC2012J000CS; Manufacturer: Samsung Electro-Mechanics; CLASS: DISCRETE; Rated Power: 0.125W, 1/8W; PCB Footprint: RESC2012X70N
UB1 UB11 = LT3015: IC REG LINEAR NEG ADJ 1.5A 8DFN; Manufacturer: Linear Technology/Analog Devices; PACK_SHORT: (IN,IN1,IN2)(OUT,OUT1)(GND,GND1)
UB2 = MOSFET_P_GSD: MOSFET P-CH 30V 4.3A SOT23; Manufacturer: Diodes Incorporated; Polarity: P-Channel; CLASS: DISCRETE
UB3 = MC7805BDTG: IC REG LINEAR 5V 1A DPAK; Company Part Status: Released; Vendor: ON Semiconductor
UB4 = BUFFER_2X_6P: IC BUF NON-INVERT 5.5V SC70-6; Manufacturer: Texas Instruments; Company Part Status: Released; Supply Voltage: 1.65V ~ 5.5V; PCB Footprint: SC70_6
UB5 = MP5000A_5: IC CURR LIMIT SWITCH; Manufacturer: Monolithic Power Systems Inc.; NC: 5; PACK_SHORT: (Source,Source2,Source3,Source4,Source5); Supply Voltage: Not Required; PCB Footprint: 10-VFDFN-thermal-V3_No_Via
UT1 = MGJ2: DC/DC CONVERTER 15V -5V 2W; Manufacturer: Murata Power Solutions Inc.; CLASS: IC; Supply Voltage: 10.8 - 13.2 V
UT6 = MGJ2: DC/DC CONVERTER 15V -5V 2W; Manufacturer: Murata Power Solutions Inc.; Supply Voltage: 10.8 - 13.2 V; CLASS: IC

## Sheet RTD.SchDoc
size 431 x 279 mm; Organization: ORGANIZATION; Address1: ADDRESS 1; Address2: ADDRESS 2; Address3: ADDRESS 3; Address4: ADDRESS 4; Revision: -; ENG_APP_DATE: --/--/--; DSN_APP_DATE: --/--/--; CHK_APP_DATE: --/--/--
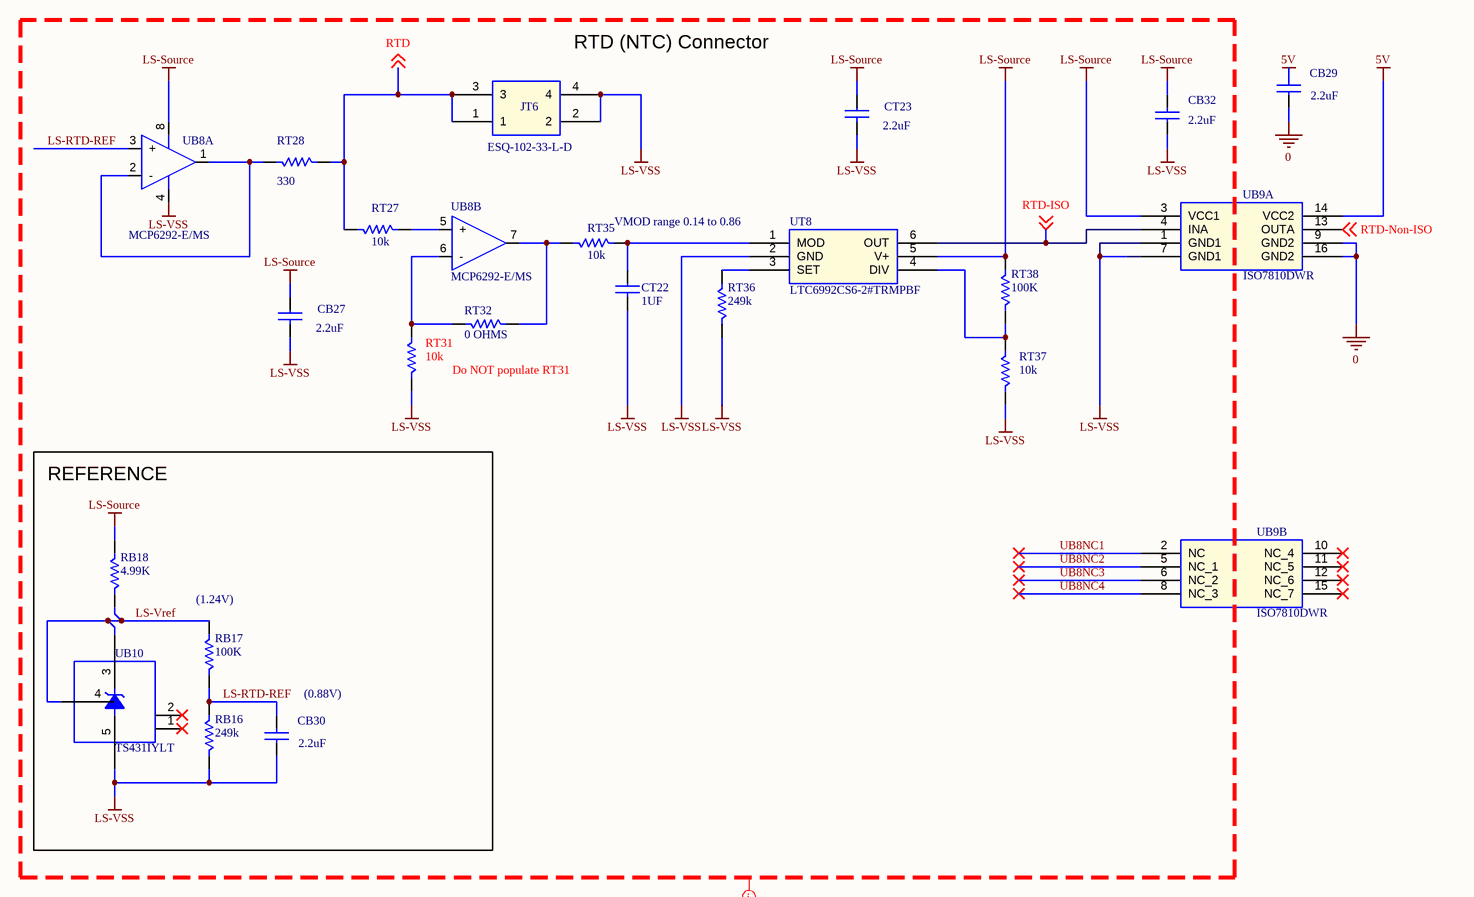
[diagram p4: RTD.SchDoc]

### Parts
CB27  2.2uF  [CAPC1608X90N]
CB29  2.2uF  [CAPC1608X90N]
CB30  2.2uF  [CAPC1608X90N]
CB32  2.2uF  [CAPC1608X90N]
CT22  1UF  [CAPC1608X90N]
CT23  2.2uF  [CAPC1608X90N]
JT6  ESQ-102-33-L-D  [CON_2x2_100mil_TH - NEW]
RB16  249k  [RESC1608X06N]
RB17  100K  [RESC1608X06N]
RB18  4.99K  [RESC1608X06N]
RT27  10k  [RESC1608X55N]
RT28  330  [RESC1608X55N]
RT31  10k  [RESC1608X55N]
RT32  0 OHMS  [RESC1608X55N]
RT35  10k  [RESC1608X55N]
RT36  249k  [RESC1608X06N]
RT37  10k  [RESC1608X55N]
RT38  100K  [RESC1608X06N]
UB8  MCP6292-E/MS  [TSOP65P580X110-8N]  (parts A,B of 2)
UB9  ISO7810DWR  [SOIC127P1030X265-16N]  (parts A,B of 2)
UB10  TS431IYLT  [SOT95P280X145-5N]
UT8  LTC6992CS6-2#TRMPBF  [SOT95P280X100-6N]

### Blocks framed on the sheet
REFERENCE: CB30 RB16-RB18 UB10

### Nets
0: CB29.1 UB9.9(GND2) UB9.16(GND2)
5V: CB29.2 UB9.14(VCC2)
LS-Source: CB27.1 CB32.2 CT23.1 RB18.1 RT38.1 UB8.8(VDD) UB9.3(VCC1) UT8.5(V+)
LS-VSS: CB27.2 CB30.1 CB32.1 CT22.2 CT23.2 JT6.2 JT6.4 RB16.2 RT31.1 RT36.2 RT37.1 UB8.4(VSS) UB9.1(GND1) UB9.7(GND1) UB10.5(C) UT8.2(GND)
LS-RTD-REF: CB30.2 RB16.1 RB17.2 UB8.3(+)
LS-Vref: RB17.1 RB18.2 UB10.3(REF) UB10.4
RTD: JT6.1 JT6.3 RT27.2 RT28.2 ; off-sheet RTD
RTD-ISO: UB9.4(INA) UT8.6(OUT) ; off-sheet RTD-ISO
RTD-Non-ISO: UB9.13(OUTA) ; off-sheet RTD-Non-ISO
UB8NC1: UB9.2(NC)
UB8NC2: UB9.5(NC_1)
UB8NC3: UB9.6(NC_2)
UB8NC4: UB9.8(NC_3)
NetCT22_1: CT22.1 RT35.1 UT8.1(MOD)
NetRT27_1: RT27.1 UB8.5(+)
NetRT28_1: RT28.1 UB8.1(VOUTA) UB8.2(-)
NetRT31_2: RT31.2 RT32.1 UB8.6(-)
NetRT32_2: RT32.2 RT35.2 UB8.7(VOUTB)
NetRT36_1: RT36.1 UT8.3(SET)
NetRT37_2: RT37.2 RT38.2 UT8.4(DIV)

Not connected (* = marked no-connect by the designer): UB9 10(NC_4)* 11(NC_5)* 12(NC_6)* 15(NC_7)*; UB10 1(NC)* 2(NC)*

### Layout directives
net class LS_Nets: LS-RTD-REF, LS-Source, LS-Vref, LS-VSS, RTD, RTD-ISO, UB8NC1, UB8NC2, UB8NC3, UB8NC4

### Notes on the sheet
- (near JT6) RTD (NTC) Connector
- (near RT35) VMOD range 0.14 to 0.86
- Do NOT populate RT31
- (near RB17) (1.24V)
- (near CB30) (0.88V)

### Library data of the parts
CB27 CT23 = CAP_2.2uF: as CB21 on sheet Differential Signaling
CB29 CB30 = CAP_2.2uF: as CB26 on sheet Differential Signaling
CB32 = CAP_2.2uF: CAP CER 2.2UF 50V X5R 0603; Manufacturer: Murata Electronics North America; Manufacturer PN: GRT188R61H225ME13D; Company Part Status: Obsolete; Tolerance: 20%; CLASS: DISCRETE
CT22 = CAP_1UF: CAP CER 1UF 10V X7R 0603; Manufacturer: Samsung; Manufacturer Part Number: CL10B105KP8NNNC; Tolerance: 10%
JT6 = CON_2x2_100mil_NEW: Conn Elevated Socket SKT 4 POS 2.54mm Solder ST Thru-Hole; Manufacturer: Samtec; PCB Footprint: CON_2x2_100mil_TH; CLASS: IO; Number of Contacts: 4; Gender: Receptacle
RB16 = RES_9_BOTTOM: RES 249K OHM 1% 1/10W 0603; Manufacturer: Yageo; Manufacturer Part Number: RC0603FR-07249KL; Voltage Rating: 50V; Resistance: 249kR; Power Rating: 100mW; Temperature Coefficient: 100ppm/°C
RB17 = RES_10B: RES SMD 100K OHM 1% 1/10W 0603; Manufacturer: TE Connectivity; Manufacturer Part Number: CRG0603F100K; Resistance: 100kR; Temperature Coefficient: 100ppm/°C; Power Rating: 100mW; Voltage Rating: 50V; Number of Resistors: 1; Class Name: LS_Components
RB18 = RES_11: RES 4.99K OHM 1% 1/10W 0603; Manufacturer: Yageo; Manufacturer Part Number: RC0603FR-074K99L; Resistance: 4.99kR; Voltage Rating: 75V; Power Rating: 100mW; Temperature Coefficient: 100ppm/°C; Voltage Rating (DC): 50V
RT27 RT35 RT37 = RES: as RB14 on sheet Differential Signaling
RT28 = RES_3: as RT4 on sheet Gate Driver
RT31 = RES: RES SMD 10K OHM 1% 1/10W 0603; Manufacturer PN: ERJ-3EKF1002V; Manufacturer: Panasonic Electronic Components; Company Part Status: New; PART_NUMBER: TMP-788; CLASS: DISCRETE; Rated Power: 0.1W, 1/10W; Temperature Coefficient: 100ppm/C; Class Name: LS_Components
RT32 = RES_12: RES 0 OHM JUMPER 0603; Manufacturer: Vishay Dale; Manufacturer Part Number: WSL060300000ZEA9; Resistance: 0mR
RT36 = RES_9_TOP: RES 249K OHM 1% 1/10W 0603; Manufacturer: Yageo; Manufacturer Part Number: RC0603FR-07249KL; Voltage Rating: 50V; Resistance: 249kR; Power Rating: 100mW; Temperature Coefficient: 100ppm/°C; Class Name: LS_Components
RT38 = RES_10: RES SMD 100K OHM 1% 1/10W 0603; Manufacturer: TE Connectivity; Manufacturer Part Number: CRG0603F100K; Resistance: 100kR; Temperature Coefficient: 100ppm/°C; Power Rating: 100mW; Voltage Rating: 50V; Number of Resistors: 1; Class Name: LS_Components
UB8 = MCP6292-E/MS: IC OPAMP GP 2 CIRCUIT 8MSOP; Manufacturer: Microchip; Number of Channels: 2; Max Supply Voltage: 5.5V; Unity Gain Bandwidth Product: 10MHz; Slew Rate: 7V/µs; Common Mode Rejection Ratio: 70dB; Min Supply Voltage: 2.4V; Voltage Gain: 110dB; Output Current: 25mA; Nominal Supply Current: 1mA; Input Bias Current: 1pA; Input Offset Voltage (Vos): 3mV; Amplifier Type: GENERAL PURPOSE; Input Offset Voltage-Max: 5mV
UB9 = ISO7810DWR: DGTL ISO 5.7KV GEN PURP 16SOIC; Company Part Status: Released; Built_By: TexasInstrumentTeam; PACK_SHORT: (GND1,GND1_1),(GND2,GND2_1); Vendor: Texas Instruments; Supply Voltage: 2.25V ~ 5.5V; CLASS: IC; PCB Footprint: DW0016B_N
UB10 = TS431IYLT: IC VREF SHUNT ADJ 2% SOT23-5; Manufacturer: STMicroelectronics; Output Voltage: 6V; Max Input Voltage: 10V; Max Output Current: 30mA; Reference Type: Shunt,Adjustable; Number of Channels: 1; Temperature Coefficient: 100ppm/°C; Cathode Current: 60uA; Output Type: Adjustable; Min Output Voltage: 1.24V
UT8 = LTC6992CS6-2: IC OSC SILICON PROG TSOT23-6; Manufacturer: Analog Devices / Linear Technology; Frequency: 3.81Hz; Min Supply Voltage: 2.25V; Max Supply Voltage: 5.5V; Number of Timers/Counters: 1; Operating Supply Current: 365uA

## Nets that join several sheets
0: Differential Signaling (27 pins), Gate Driver (20 pins), Power Supplies (17 pins), RTD (CB29.1 UB9.9 UB9.16)
5V: Differential Signaling (14 pins), Gate Driver (12 pins), Power Supplies (5 pins), RTD (CB29.2 UB9.14)
HS-Source: Gate Driver (16 pins), Power Supplies (8 pins)
HS-VDD: Gate Driver (CB3.1 CB6.1 RT1.1 UT2.13), Power Supplies (CT1.1 UT1.7)
HS-VSS: Gate Driver (CB2.2 CB5.2 UT2.9 UT2.16), Power Supplies (7 pins)
LS-Source: Gate Driver (15 pins), Power Supplies (8 pins), RTD (8 pins)
LS-VDD: Gate Driver (CB33.1 CB37.1 RT40.1 UT7.13), Power Supplies (CT25.1 UT6.7)
LS-VSS: Gate Driver (CB34.2 CB36.2 UT7.9 UT7.16), Power Supplies (7 pins), RTD (16 pins)
Unprotected_Vin: Differential Signaling (JT4.1), Power Supplies (DB3.C UB2.3)
FLT_HS: Differential Signaling (RT9.1), Gate Driver (CT7.1 DT4.2 RT16.2 UT2.5)
FLT_LS: Differential Signaling (RT11.1), Gate Driver (CT18.1 DT6.2 RT19.2 UT7.5)
HS-PWM: Differential Signaling (UT5.7), Gate Driver (RT8.1)
LS-PWM: Differential Signaling (UT5.3), Gate Driver (RT30.1)
PS-Dis: Differential Signaling (JT4.11), Power Supplies (RB7.2)
RDY_HS: Differential Signaling (RT12.1), Gate Driver (CT6.1 RT14.2 RT17.2 UT2.4)
RDY_LS: Differential Signaling (RT13.1), Gate Driver (CT19.1 RT18.2 RT20.2 UT7.4)
Reset: Differential Signaling (UB7.4), Gate Driver (RT7.1 RT29.1)
RTD-Non-ISO: Differential Signaling (UB6.9), RTD (UB9.13)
